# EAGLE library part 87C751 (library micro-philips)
83C751/87C751 80C51 with I2C bus, 8-bit Microcontroller 2K/64 OTP/ROM
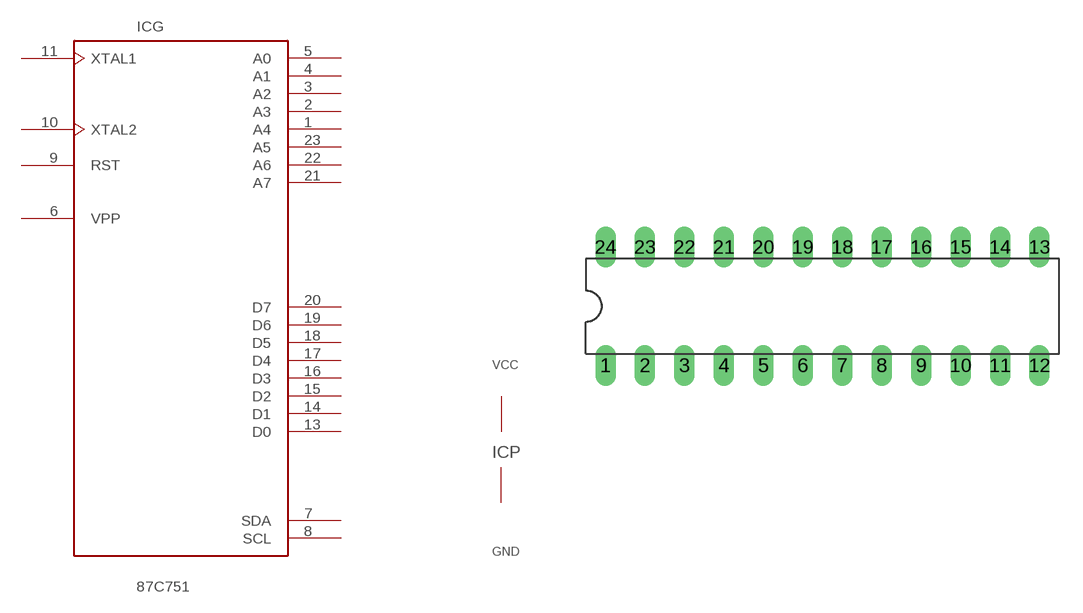
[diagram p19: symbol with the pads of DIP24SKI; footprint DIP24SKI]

Designator prefix IC; gates G=8XC751 P=PWR2

## 87C751 (OC_FARNELL: unknown; OC_NEWARK: unknown)  [DIP24SKI]
1  G:A4
2  G:A3
3  G:A2
4  G:A1
5  G:A0
6  G:VPP  pwr
7  G:SDA
8  G:SCL
9  G:RST  in
10  G:XTAL2  in
11  G:XTAL1  in
12  P:GND  pwr
13  G:D0
14  G:D1
15  G:D2
16  G:D3
17  G:D4
18  G:D5
19  G:D6
20  G:D7
21  G:A7
22  G:A6
23  G:A5
24  P:VCC  pwr

## Footprint DIP24SKI (pad centres in mm)
Dual In Line
drill 0.813 pad 1.27 long: 1 -11.43,-3.81; 2 -8.89,-3.81; 3 -6.35,-3.81; 4 -3.81,-3.81; 5 -1.27,-3.81; 6 1.27,-3.81; 7 3.81,-3.81; 8 6.35,-3.81; 9 8.89,-3.81; 10 11.43,-3.81; 11 13.97,-3.81; 12 16.51,-3.81; 13 16.51,3.81; 14 13.97,3.81; 15 11.43,3.81; 16 8.89,3.81; 17 6.35,3.81; 18 3.81,3.81; 19 1.27,3.81; 20 -1.27,3.81; 21 -3.81,3.81; 22 -6.35,3.81; 23 -8.89,3.81; 24 -11.43,3.81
